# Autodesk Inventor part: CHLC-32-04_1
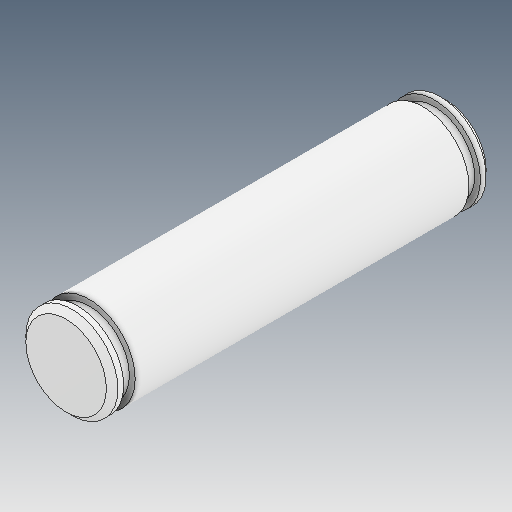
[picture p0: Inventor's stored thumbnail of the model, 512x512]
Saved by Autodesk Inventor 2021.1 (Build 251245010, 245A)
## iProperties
Created: 2021-05
Part Number: CHLC-32-04_1
Material: Ogólny
Document SubType Name: Modeling
Designer: user
Density: 1 g/cm^3
Appearance: Domyślna
Author: user
Revision Number: ÈÎºÎ
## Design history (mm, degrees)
feature "ÊäÈë1"
node "Bryła1"
